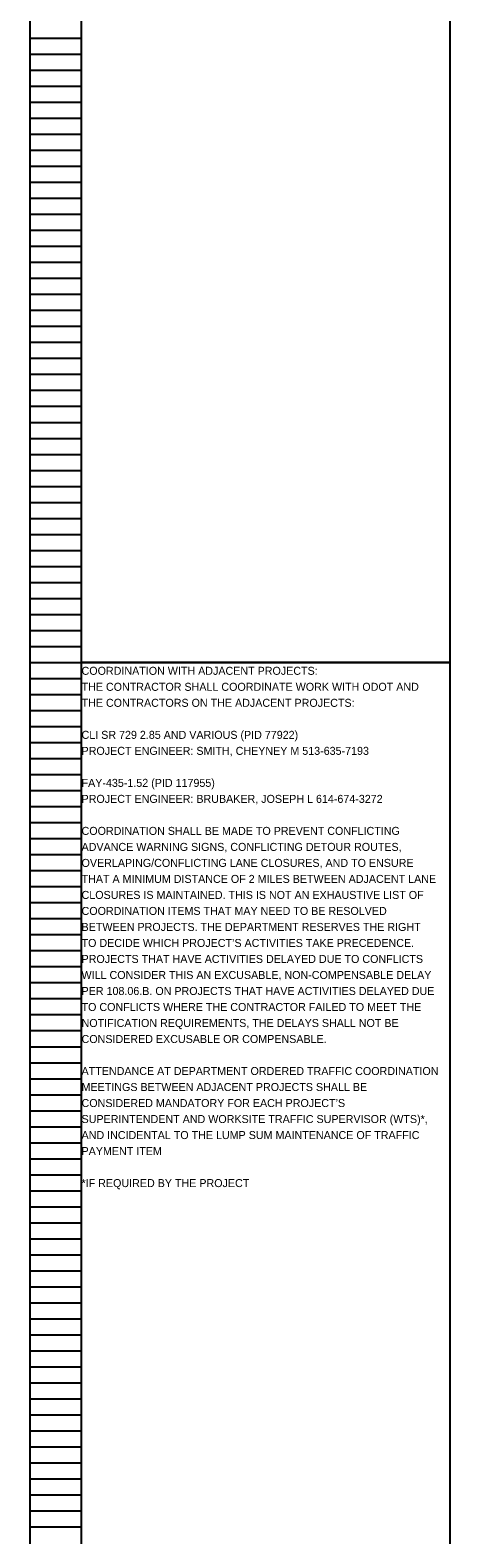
# Model space of a CAD drawing. Extents: x 16463 to 16500, y 5400 to 5823.
# Drawn here: x 16463.05 to 16470.39, y 5505.81 to 5532.13 of the extents above; entities that cross this region are included whole.
import ezdxf

# ---------------------------------------------------------------- set-up
doc = ezdxf.new("R2010")
doc.units = 0
for name, color, linetype in [('SC_Scratch1', 7, 'Continuous'), ('SH_Data', 7, 'Continuous'), ('SH_Text', 7, 'Continuous')]:
    doc.layers.add(name, color=color, linetype=linetype)

msp = doc.modelspace()

# ---------------------------------------------------------------- linework, layer by layer
at = {"layer": 'SC_Scratch1'}
for points in [[(16463.949, 5541.232), (16470.389, 5541.232), (16470.389, 5521.072), (16463.949, 5521.072)], [(16463.949, 5521.072), (16470.389, 5521.072), (16470.389, 5500.912), (16463.949, 5500.912)]]:
    msp.add_lwpolyline(points, close=True, dxfattribs=at)
at = {"layer": 'SH_Data'}
for p, q in [((16463.049, 5521.072), (16463.049, 5541.232)), ((16463.949, 5521.072), (16463.949, 5541.232)), ((16463.049, 5531.992), (16463.949, 5531.992)), ((16463.049, 5531.712), (16463.949, 5531.712)), ((16463.049, 5531.432), (16463.949, 5531.432)), ((16463.049, 5531.152), (16463.949, 5531.152)), ((16463.049, 5530.872), (16463.949, 5530.872)), ((16463.049, 5530.592), (16463.949, 5530.592)), ((16463.049, 5530.312), (16463.949, 5530.312)), ((16463.049, 5530.032), (16463.949, 5530.032)), ((16463.049, 5529.752), (16463.949, 5529.752)), ((16463.049, 5529.472), (16463.949, 5529.472)), ((16463.049, 5529.192), (16463.949, 5529.192)), ((16463.049, 5528.912), (16463.949, 5528.912)), ((16463.049, 5528.632), (16463.949, 5528.632)), ((16463.049, 5528.352), (16463.949, 5528.352)), ((16463.049, 5528.072), (16463.949, 5528.072)), ((16463.049, 5527.792), (16463.949, 5527.792)), ((16463.049, 5527.512), (16463.949, 5527.512)), ((16463.049, 5527.232), (16463.949, 5527.232)), ((16463.049, 5526.952), (16463.949, 5526.952)), ((16463.049, 5526.672), (16463.949, 5526.672)), ((16463.049, 5526.392), (16463.949, 5526.392)), ((16463.049, 5526.112), (16463.949, 5526.112)), ((16463.049, 5525.832), (16463.949, 5525.832)), ((16463.049, 5525.552), (16463.949, 5525.552)), ((16463.049, 5525.272), (16463.949, 5525.272)), ((16463.049, 5524.992), (16463.949, 5524.992)), ((16463.049, 5524.712), (16463.949, 5524.712)), ((16463.049, 5524.432), (16463.949, 5524.432)), ((16463.049, 5524.152), (16463.949, 5524.152)), ((16463.049, 5523.872), (16463.949, 5523.872)), ((16463.049, 5523.592), (16463.949, 5523.592)), ((16463.049, 5523.312), (16463.949, 5523.312)), ((16463.049, 5523.032), (16463.949, 5523.032)), ((16463.049, 5522.752), (16463.949, 5522.752)), ((16463.049, 5522.472), (16463.949, 5522.472)), ((16463.049, 5522.192), (16463.949, 5522.192)), ((16463.049, 5521.912), (16463.949, 5521.912)), ((16463.049, 5521.632), (16463.949, 5521.632)), ((16463.049, 5521.352), (16463.949, 5521.352)), ((16463.049, 5500.912), (16463.049, 5521.072)), ((16463.049, 5521.072), (16463.949, 5521.072)), ((16463.049, 5521.072), (16463.949, 5521.072)), ((16463.949, 5500.912), (16463.949, 5521.072)), ((16463.049, 5520.792), (16463.949, 5520.792)), ((16463.049, 5520.512), (16463.949, 5520.512)), ((16463.049, 5520.232), (16463.949, 5520.232)), ((16463.049, 5519.952), (16463.949, 5519.952)), ((16463.049, 5519.672), (16463.949, 5519.672)), ((16463.049, 5519.392), (16463.949, 5519.392)), ((16463.049, 5519.112), (16463.949, 5519.112)), ((16463.049, 5518.832), (16463.949, 5518.832)), ((16463.049, 5518.552), (16463.949, 5518.552)), ((16463.049, 5518.272), (16463.949, 5518.272)), ((16463.049, 5517.992), (16463.949, 5517.992)), ((16463.049, 5517.712), (16463.949, 5517.712)), ((16463.049, 5517.432), (16463.949, 5517.432)), ((16463.049, 5517.152), (16463.949, 5517.152)), ((16463.049, 5516.872), (16463.949, 5516.872)), ((16463.049, 5516.592), (16463.949, 5516.592)), ((16463.049, 5516.312), (16463.949, 5516.312)), ((16463.049, 5516.032), (16463.949, 5516.032)), ((16463.049, 5515.752), (16463.949, 5515.752)), ((16463.049, 5515.472), (16463.949, 5515.472)), ((16463.049, 5515.192), (16463.949, 5515.192)), ((16463.049, 5514.912), (16463.949, 5514.912)), ((16463.049, 5514.632), (16463.949, 5514.632)), ((16463.049, 5514.352), (16463.949, 5514.352)), ((16463.049, 5514.072), (16463.949, 5514.072)), ((16463.049, 5513.792), (16463.949, 5513.792)), ((16463.049, 5513.512), (16463.949, 5513.512)), ((16463.049, 5513.232), (16463.949, 5513.232)), ((16463.049, 5512.952), (16463.949, 5512.952)), ((16463.049, 5512.672), (16463.949, 5512.672)), ((16463.049, 5512.392), (16463.949, 5512.392)), ((16463.049, 5512.112), (16463.949, 5512.112)), ((16463.049, 5511.832), (16463.949, 5511.832)), ((16463.049, 5511.552), (16463.949, 5511.552)), ((16463.049, 5511.272), (16463.949, 5511.272)), ((16463.049, 5510.992), (16463.949, 5510.992)), ((16463.049, 5510.712), (16463.949, 5510.712)), ((16463.049, 5510.432), (16463.949, 5510.432)), ((16463.049, 5510.152), (16463.949, 5510.152)), ((16463.049, 5509.872), (16463.949, 5509.872)), ((16463.049, 5509.592), (16463.949, 5509.592)), ((16463.049, 5509.312), (16463.949, 5509.312)), ((16463.049, 5509.032), (16463.949, 5509.032)), ((16463.049, 5508.752), (16463.949, 5508.752)), ((16463.049, 5508.472), (16463.949, 5508.472)), ((16463.049, 5508.192), (16463.949, 5508.192)), ((16463.049, 5507.912), (16463.949, 5507.912)), ((16463.049, 5507.632), (16463.949, 5507.632)), ((16463.049, 5507.352), (16463.949, 5507.352)), ((16463.049, 5507.072), (16463.949, 5507.072)), ((16463.049, 5506.792), (16463.949, 5506.792)), ((16463.049, 5506.512), (16463.949, 5506.512)), ((16463.049, 5506.232), (16463.949, 5506.232)), ((16463.049, 5505.952), (16463.949, 5505.952))]:
    msp.add_line(p, q, dxfattribs=at)

# ---------------------------------------------------------------- texts
at = {"layer": 'SH_Text'}
for s, p in [('COORDINATION WITH ADJACENT PROJECTS:', (16463.949, 5520.856)), ('THE CONTRACTOR SHALL COORDINATE WORK WITH ODOT AND ', (16463.949, 5520.576)), ('THE CONTRACTORS ON THE ADJACENT PROJECTS: ', (16463.949, 5520.296)), ('CLI SR 729 2.85 AND VARIOUS (PID 77922) ', (16463.949, 5519.736)), ('PROJECT ENGINEER: SMITH, CHEYNEY M 513-635-7193', (16463.949, 5519.456)), ('FAY-435-1.52 (PID 117955)', (16463.949, 5518.896)), ('PROJECT ENGINEER: BRUBAKER, JOSEPH L 614-674-3272', (16463.949, 5518.616)), ('COORDINATION SHALL BE MADE TO PREVENT CONFLICTING ', (16463.949, 5518.056)), ('ADVANCE WARNING SIGNS, CONFLICTING DETOUR ROUTES, ', (16463.949, 5517.776)), ('OVERLAPING/CONFLICTING LANE CLOSURES, AND TO ENSURE ', (16463.949, 5517.496)), ('THAT A MINIMUM DISTANCE OF 2 MILES BETWEEN ADJACENT LANE ', (16463.949, 5517.216)), ('CLOSURES IS MAINTAINED. THIS IS NOT AN EXHAUSTIVE LIST OF ', (16463.949, 5516.936)), ('COORDINATION ITEMS THAT MAY NEED TO BE RESOLVED ', (16463.949, 5516.656)), ('BETWEEN PROJECTS. THE DEPARTMENT RESERVES THE RIGHT ', (16463.949, 5516.376)), ('TO DECIDE WHICH PROJECT’S ACTIVITIES TAKE PRECEDENCE. ', (16463.949, 5516.096)), ('PROJECTS THAT HAVE ACTIVITIES DELAYED DUE TO CONFLICTS ', (16463.949, 5515.816)), ('WILL CONSIDER THIS AN EXCUSABLE, NON-COMPENSABLE DELAY ', (16463.949, 5515.536)), ('PER 108.06.B. ON PROJECTS THAT HAVE ACTIVITIES DELAYED DUE ', (16463.949, 5515.256)), ('TO CONFLICTS WHERE THE CONTRACTOR FAILED TO MEET THE ', (16463.949, 5514.976)), ('NOTIFICATION REQUIREMENTS, THE DELAYS SHALL NOT BE ', (16463.949, 5514.696)), ('CONSIDERED EXCUSABLE OR COMPENSABLE.', (16463.949, 5514.416)), ('ATTENDANCE AT DEPARTMENT ORDERED TRAFFIC COORDINATION ', (16463.949, 5513.856)), ('MEETINGS BETWEEN ADJACENT PROJECTS SHALL BE ', (16463.949, 5513.576)), ('CONSIDERED MANDATORY FOR EACH PROJECT’S ', (16463.949, 5513.296)), ('SUPERINTENDENT AND WORKSITE TRAFFIC SUPERVISOR (WTS)*, ', (16463.949, 5513.016)), ('AND INCIDENTAL TO THE LUMP SUM MAINTENANCE OF TRAFFIC ', (16463.949, 5512.736)), ('PAYMENT ITEM', (16463.949, 5512.456)), ('*IF REQUIRED BY THE PROJECT', (16463.949, 5511.896))]:
    msp.add_text(s, height=0.14, dxfattribs=at).set_placement(p)

doc.saveas('drawing.dxf')
